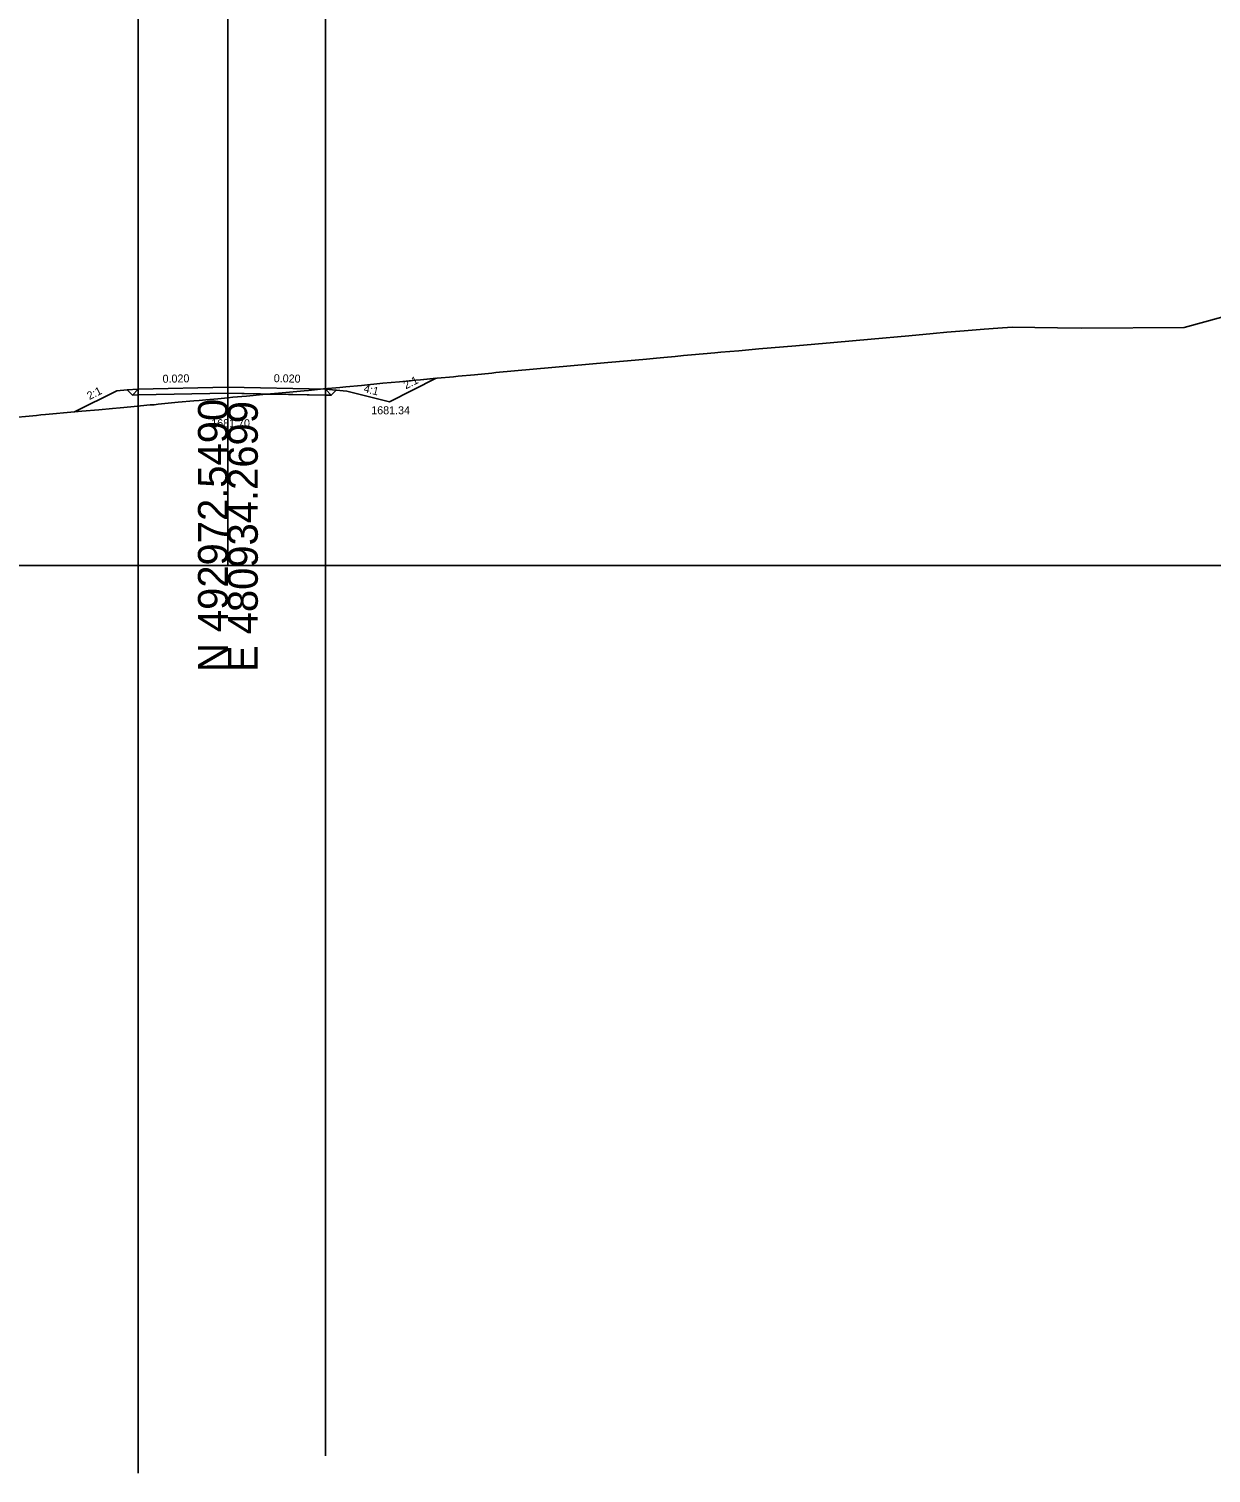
# Model space of a CAD drawing. Extents: x -26 to 403, y -88 to 5647.
# Drawn here: x 181.4 to 292.1, y 5414.9 to 5550.3 of the extents above; entities that cross this region are included whole.
import ezdxf

# ---------------------------------------------------------------- set-up
doc = ezdxf.new("R2010")
doc.units = 0
for name, color, linetype in [('Exist Cross Section Cell', 7, 'Continuous'), ('Exist XS Center Line Elevation Label', 7, 'Continuous'), ('Exist XS Ground Line', 7, 'Continuous'), ('Prop Road Sect_ Boring - Material (Outline)', 7, 'Continuous'), ('Prop XS Ditch Slope Text', 7, 'Continuous'), ('Prop XS Ditch Standard Text', 7, 'Continuous'), ('Prop XS Dump Level', 7, 'Continuous'), ('Prop XS Earthwork Shape', 7, 'Continuous'), ('Prop XS EOT Tick Mark', 7, 'Continuous'), ('Prop XS Finish Grade', 7, 'Continuous'), ('Prop XS Finish Grade Earthwork', 7, 'Continuous'), ('Prop XS Finish Grade Pavement', 7, 'Continuous'), ('Prop XS Hydro Typical Ditch Data', 7, 'Continuous'), ('Prop XS Pvmt Edge Slope', 7, 'Continuous'), ('Prop XS SE Text', 7, 'Continuous'), ('Prop XS Side Slope Text', 7, 'Continuous'), ('Prop XS Subgrade Earthwork', 7, 'Continuous'), ('Scratch_Level_7', 7, 'Continuous')]:
    doc.layers.add(name, color=color, linetype=linetype)

msp = doc.modelspace()

# ---------------------------------------------------------------- linework, layer by layer
at = {"layer": 'Exist Cross Section Cell'}
for p, q in [((200, 5500), (200, 5643.88)), ((0, 5500), (200, 5500)), ((200, 5500), (400, 5500))]:
    msp.add_line(p, q, dxfattribs=at)
at = {"layer": 'Exist XS Ground Line'}
msp.add_lwpolyline([(179.29, 5513.81), (182.06, 5514.06), (182.49, 5514.1), (182.92, 5514.14), (185.62, 5514.38), (186.33, 5514.44), (187.92, 5514.59), (189.19, 5514.7), (189.92, 5514.76), (190.92, 5514.86), (192.71, 5515.03), (193.08, 5515.06), (193.47, 5515.1), (195.35, 5515.28), (196.81, 5515.41), (197.32, 5515.46), (197.94, 5515.52), (199.05, 5515.62), (200, 5515.7), (200.46, 5515.75), (201.74, 5515.87), (203.27, 5516), (204.01, 5516.07), (205.42, 5516.21), (207.16, 5516.36), (207.54, 5516.4), (208.96, 5516.53), (210.48, 5516.67), (211.04, 5516.73), (212.51, 5516.86), (214.52, 5517.06), (216.06, 5517.2), (217.6, 5517.35), (218.03, 5517.39), (219.59, 5517.54), (221.14, 5517.68), (221.58, 5517.73), (223.11, 5517.87), (224.71, 5518.02), (225.11, 5518.06), (228.61, 5518.38), (232.1, 5518.7), (235.58, 5519.02), (237.43, 5519.18), (239.2, 5519.33), (240.16, 5519.43), (240.83, 5519.49), (241.9, 5519.59), (242.68, 5519.67), (243.43, 5519.73), (245.61, 5519.93), (246.16, 5519.98), (247.85, 5520.11), (249.73, 5520.29), (253.21, 5520.58), (256.75, 5520.88), (260.27, 5521.2), (263.77, 5521.52), (266.05, 5521.72), (267.33, 5521.84), (268.97, 5521.97), (270.83, 5522.14), (272.11, 5522.23), (273.46, 5522.33), (277.7, 5522.27), (279.99, 5522.24), (289.58, 5522.3), (298.23, 5524.66)], dxfattribs=at)
at = {"layer": 'Prop Road Sect_ Boring - Material (Outline)'}
for points in [[(191.6, 5516.52), (191.05, 5515.96), (190.58, 5516.44)], [(209.68, 5515.95), (210.15, 5516.42), (209.13, 5516.5)]]:
    msp.add_lwpolyline(points, close=True, dxfattribs=at)
at = {"layer": 'Prop XS Dump Level'}
for p, q in [((191.6, 5516.52), (200, 5516.69)), ((200, 5516.69), (209.13, 5516.5))]:
    msp.add_line(p, q, dxfattribs=at)
at = {"layer": 'Prop XS Earthwork Shape'}
for points in [[(203.95, 5516.06), (204.01, 5516.07), (205.42, 5516.21), (207.16, 5516.36), (207.54, 5516.4), (208.96, 5516.53), (210.48, 5516.67), (211.04, 5516.73), (212.51, 5516.86), (214.52, 5517.06), (216.06, 5517.2), (217.6, 5517.35), (218.03, 5517.39), (219.5, 5517.53), (215.13, 5515.34), (211.13, 5516.34), (210.15, 5516.42), (209.68, 5515.95), (209.13, 5515.96)], [(185.64, 5514.38), (186.33, 5514.44), (187.92, 5514.59), (189.19, 5514.7), (189.92, 5514.76), (190.92, 5514.86), (192.71, 5515.03), (193.08, 5515.06), (193.47, 5515.1), (195.35, 5515.28), (196.81, 5515.41), (197.32, 5515.46), (197.94, 5515.52), (199.05, 5515.62), (200, 5515.7), (200.46, 5515.75), (201.74, 5515.87), (203.27, 5516), (203.95, 5516.06), (200, 5516.14), (191.6, 5515.98), (191.05, 5515.96), (190.58, 5516.44), (189.6, 5516.36)]]:
    msp.add_lwpolyline(points, close=True, dxfattribs=at)
at = {"layer": 'Prop XS EOT Tick Mark'}
for p, q in [((191.6, 5516.52), (191.6, 5517.52)), ((209.13, 5516.5), (209.13, 5517.5))]:
    msp.add_line(p, q, dxfattribs=at)
at = {"layer": 'Prop XS Finish Grade'}
for p, q in [((191.6, 5516.52), (190.58, 5516.44)), ((209.13, 5516.5), (210.15, 5516.42))]:
    msp.add_line(p, q, dxfattribs=at)
at = {"layer": 'Prop XS Finish Grade Earthwork'}
for p, q in [((215.13, 5515.34), (219.5, 5517.53)), ((189.6, 5516.36), (185.64, 5514.38)), ((190.58, 5516.44), (189.6, 5516.36)), ((210.15, 5516.42), (211.13, 5516.34)), ((211.13, 5516.34), (215.13, 5515.34))]:
    msp.add_line(p, q, dxfattribs=at)
at = {"layer": 'Prop XS Finish Grade Pavement'}
for p, q in [((191.6, 5516.52), (200, 5516.69)), ((200, 5516.69), (209.13, 5516.5))]:
    msp.add_line(p, q, dxfattribs=at)
at = {"layer": 'Prop XS Hydro Typical Ditch Data'}
for p, q in [((215.13, 5515.34), (219.5, 5517.53)), ((211.13, 5516.34), (215.13, 5515.34))]:
    msp.add_line(p, q, dxfattribs=at)
at = {"layer": 'Prop XS Pvmt Edge Slope'}
for p, q in [((191.6, 5516.52), (191.05, 5515.96)), ((209.13, 5516.5), (209.68, 5515.95))]:
    msp.add_line(p, q, dxfattribs=at)
at = {"layer": 'Prop XS Subgrade Earthwork'}
for p, q in [((191.05, 5515.96), (190.58, 5516.44)), ((191.6, 5515.98), (191.05, 5515.96)), ((200, 5516.14), (191.6, 5515.98)), ((209.13, 5515.96), (200, 5516.14)), ((209.13, 5515.96), (209.68, 5515.95)), ((209.68, 5515.95), (210.15, 5516.42))]:
    msp.add_line(p, q, dxfattribs=at)
at = {"layer": 'Scratch_Level_7'}
for p, q in [((209.13, 5616.55), (209.13, 5416.55)), ((191.6, 5614.93), (191.6, 5414.93))]:
    msp.add_line(p, q, dxfattribs=at)

# ---------------------------------------------------------------- texts
at = {"layer": 'Exist Cross Section Cell'}
for s, p in [('N 492972.5490', (200, 5490)), ('E 480934.2699', (202.8, 5490))]:
    msp.add_text(s, height=2.8, rotation=90, dxfattribs=at).set_placement(p)
at = {"layer": 'Exist XS Center Line Elevation Label'}
msp.add_text('1681.70', height=0.75, dxfattribs=at).set_placement((198.44, 5512.95))
at = {"layer": 'Prop XS Ditch Slope Text'}
for s, rotation, p in [('2:1', 26.5651, (187.03, 5515.49)), ('4:1', 345.9638, (212.67, 5516.25))]:
    msp.add_text(s, height=0.75, rotation=rotation, dxfattribs=at).set_placement(p)
at = {"layer": 'Prop XS Ditch Standard Text'}
msp.add_text('1681.34', height=0.75, dxfattribs=at).set_placement((213.43, 5514.16))
at = {"layer": 'Prop XS Dump Level'}
for p in [(189.6, 5516.32), (211.13, 5516.3), (211.13, 5516.3)]:
    msp.add_text('Case1', height=0.04, dxfattribs=at).set_placement(p)
at = {"layer": 'Prop XS SE Text'}
for rotation, p in [(1.1458, (193.89, 5517.11)), (358.8542, (204.29, 5517.17))]:
    msp.add_text('0.020', height=0.75, rotation=rotation, dxfattribs=at).set_placement(p)
at = {"layer": 'Prop XS Side Slope Text'}
msp.add_text('2:1', height=0.75, rotation=26.5651, dxfattribs=at).set_placement((216.67, 5516.49))

doc.saveas('drawing.dxf')
